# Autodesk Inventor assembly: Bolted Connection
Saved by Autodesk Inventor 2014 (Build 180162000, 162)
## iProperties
Created: 2010-12
Part Number: Bolted Connection
Document SubType Name: Assembly
Designer: Thom Tremblay
ClientObjectVersion: 1
Author: Thom Tremblay
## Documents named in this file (3)
- C:\Inventor 2014 Essentials\Assemblies\Chapter 08\c08-01\Design Accelerator\Bolted Connection4.iam
- C:\Inventor 2014 Essentials\Content Center Files\en-US\ISO 7091\ISO 7091 - ST 4 - 100 HV.ipt
- C:\Inventor 2014 Essentials\Content Center Files\en-US\ISO 4017\ISO 4017 - M4 x 8ISO.ipt
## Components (2 placed, 2 different names)
1. ISO 7091 ST 4 - 100 HV:1
2. ISO 4017 M4 x 8:1
